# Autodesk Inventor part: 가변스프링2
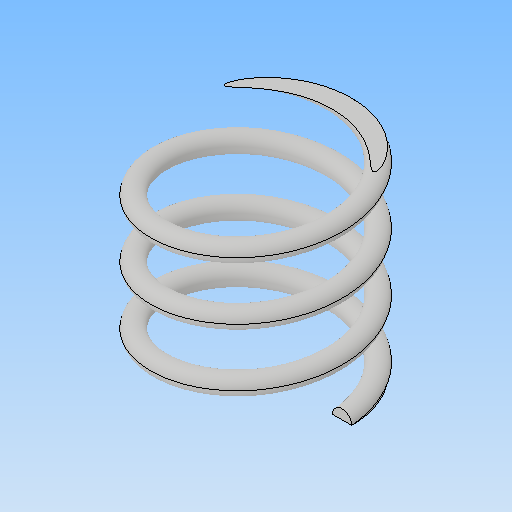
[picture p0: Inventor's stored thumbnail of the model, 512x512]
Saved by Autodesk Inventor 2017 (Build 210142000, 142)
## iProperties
Part Number: 가변스프링2
Material: 일반
Document SubType Name: Modeling
Designer: MRC
Density: 1 g/cm^3
Appearance: 기본값
Author: MRC
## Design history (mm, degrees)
sketch "스케치1"
  geometry: L1 (0, 0)-(0, 19.5); L2 (0, 19.5)-(9, 19.5); L3 (0, 0)-(9, 0); C1 r 1 at (9, 0)
  constraints: 6 end point, 1 centre point, 1 coincident, 1 parallel, 1 perpendicular, 1 vertical
  dimensions: "d0" = 19.5 distance of L1.start L1.end (derived); "d1" = 9 distance of L1.end L2.end; "d2" = 9 distance of L1.start L3.end; "d3" = 2 diameter of C1
feature "코일1" sketch "스케치1" pitch "d4" = 10; turns "d6" = 5; dims "d5" = 30, "d7" = 0, angle "d8" = 90 deg, angle "d9" = 90 deg, "d10" = 0, "d11" = 0
sketch "스케치2"
  geometry: L1 (19.5, 15.094)-(0, 15.094); L2 (0, 15.094)-(0, -15.094); L3 (0, -15.094)-(19.5, -15.094); L4 (19.5, -15.094)-(19.5, 15.094); 3 further points
  constraints: 8 end point, 2 midpoint, 2 parallel, 1 coincident, 1 horizontal, 1 horizontal alignment, 1 perpendicular
  dimensions: "d12" = 19.5 distance of L2.end L3.end (= d0); "d13" = 30.18785 distance of L3.end L1.start
extrude "돌출1" sketch "스케치2" stored distance "d14" = 0; taper "d15" = 0 deg
node "솔리드1"
